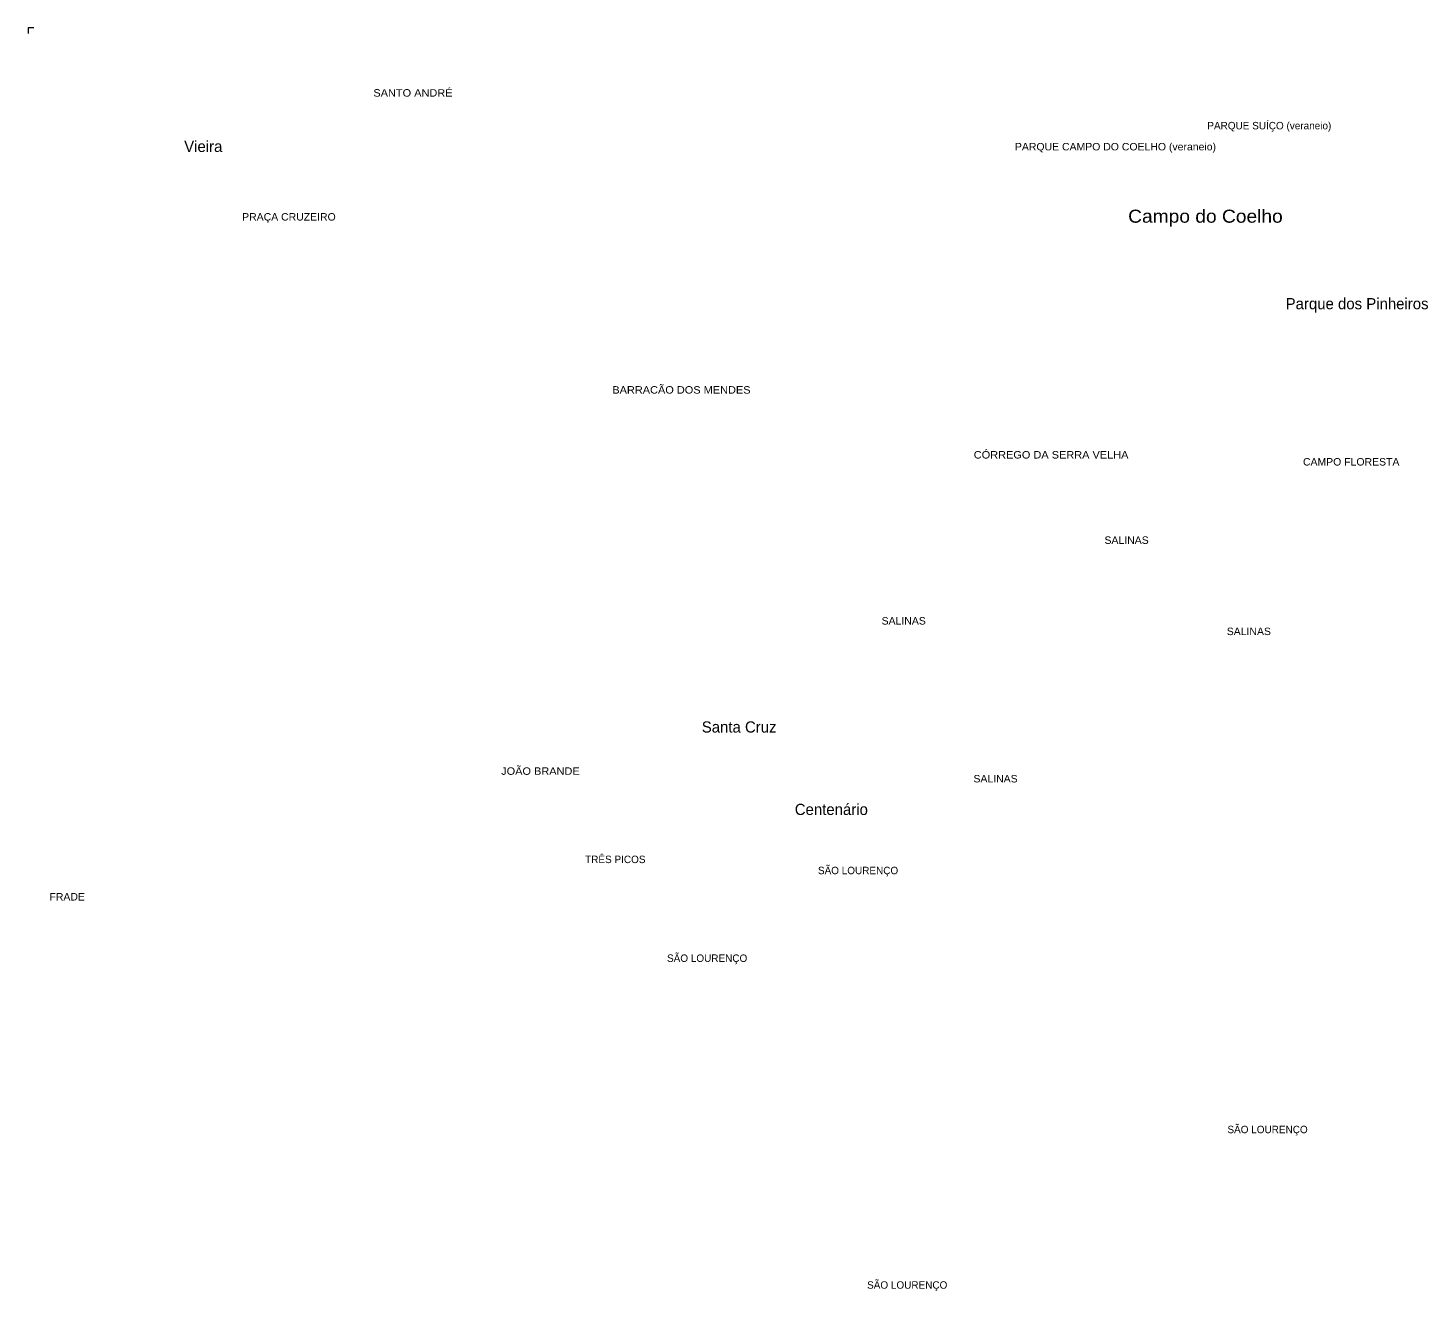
# Model space of a CAD drawing. Extents: x 731.5 to 757.7, y 7509.7 to 7537.8.
# Drawn here: x 731.88 to 746.91, y 7524.2 to 7537.77 of the extents above; entities that cross this region are included whole.
import ezdxf
from ezdxf.enums import TextEntityAlignment as Align

# ---------------------------------------------------------------- set-up
doc = ezdxf.new("R2010")
doc.units = 0
doc.header["$LTSCALE"] = 0.032
doc.layers.add('56', color=7, linetype='Continuous')
doc.layers.add('61', color=7, linetype='Continuous')
doc.layers.add('63', color=7, linetype='Continuous', lineweight=13)

msp = doc.modelspace()

# ---------------------------------------------------------------- linework, layer by layer
at = {"layer": '63'}
msp.add_lwpolyline([(731.9429, 7537.7681), (731.8813, 7537.7681), (731.8813, 7537.7074)], dxfattribs=at)

# ---------------------------------------------------------------- texts
at = {"layer": '56'}
for s, width, p in [('SANTO ANDRÉ', 1.1, (736.0149, 7537.0308)), ('PARQUE CAMPO DO COELHO (veraneio)', 1.05, (743.5584, 7536.453)), ('PRAÇA CRUZEIRO', 1.05, (734.6832, 7535.6992)), ('BARRACÃO DOS MENDES', 1.1, (738.8977, 7533.8401)), ('CÓRREGO DA SERRA VELHA', 1.1, (742.8672, 7533.1428)), ('CAMPO FLORESTA', 1.05, (746.0895, 7533.0674)), ('SALINAS', 1.05, (743.6776, 7532.2257)), ('SALINAS', 1.05, (741.2845, 7531.3589)), ('SALINAS', 1.05, (744.9905, 7531.2458)), ('JOÃO BRANDE', 1.1, (737.3837, 7529.7447)), ('SALINAS', 1.05, (742.2707, 7529.6629)), ('FRADE', 1.05, (732.3022, 7528.3943))]:
    msp.add_text(s, height=0.08, dxfattribs=dict(at, width=width)).set_placement(p, align=Align.CENTER)
for s, p in [('PARQUE SUÍÇO (veraneio)', (745.2104, 7536.6791)), ('TRÊS PICOS', (738.1877, 7528.7962)), ('SÃO LOURENÇO', (740.7944, 7528.6769)), ('SÃO LOURENÇO', (739.1739, 7527.7347)), ('SÃO LOURENÇO', (745.1914, 7525.8945)), ('SÃO LOURENÇO', (741.3221, 7524.2237))]:
    msp.add_text(s, height=0.08, dxfattribs=at).set_placement(p, align=Align.CENTER)
at = {"layer": '61'}
for s, p in [('Vieira', (733.5584, 7536.436)), ('Parque dos Pinheiros', (745.3857, 7534.7465)), ('Santa Cruz', (739.1161, 7530.1989)), ('Centenário', (740.1148, 7529.3132))]:
    msp.add_text(s, height=0.12, dxfattribs=at).set_placement(p)
at = {"layer": '61', "width": 1.1}
msp.add_text('Campo do Coelho', height=0.14, dxfattribs=at).set_placement((745.3545, 7535.6762), align=Align.RIGHT)

doc.saveas('drawing.dxf')
